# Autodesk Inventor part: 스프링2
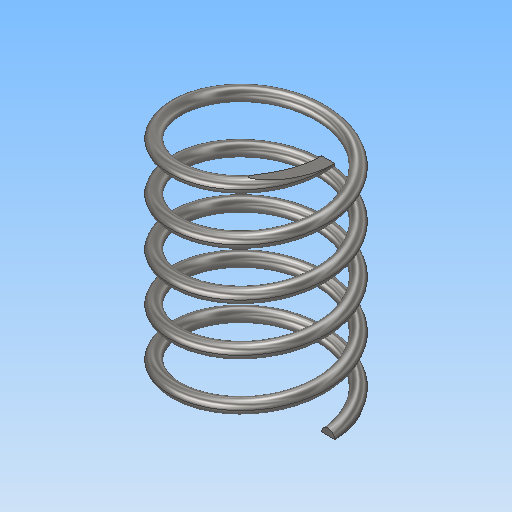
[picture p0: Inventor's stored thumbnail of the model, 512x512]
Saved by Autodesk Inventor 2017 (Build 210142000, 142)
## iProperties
Part Number: 스프링2
Material: 강철, 연강
Document SubType Name: Modeling
Designer: MRC
Density: 7.85 g/cm^3
Appearance: 반연마
Mass: 8.42324 g
Surface Area: 21.7217 cm^2
Volume: 1.07302 cm^3
Author: MRC
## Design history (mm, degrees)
sketch "스케치1"
  geometry: L1 (0, 0)-(0, 36.411); L2 (0, 36.411)-(11, 36.411); L3 (0, 0)-(11, 0); C1 r 1 at (11, 0)
  constraints: 6 end point, 2 horizontal, 1 centre point, 1 coincident, 1 vertical
  dimensions: "d0" = 36.4112 distance of L1.start L1.end (derived); "d2" = 22 diameter of L3.end L1; "d3" = 2 diameter of C1; "d4" = 22 diameter of L2.end L1
feature "코일1" pitch "d5" = 10; turns "d7" = 5; dims "d6" = 36.4112 (= d0), "d8" = 0, angle "d9" = 90 deg, angle "d10" = 90 deg, "d11" = 0, "d12" = 0
sketch "스케치2"
  geometry: L1 (-13.313, 0)-(15.035, 0); L2 (15.035, 0)-(15.035, 36.411); L3 (15.035, 36.411)-(-13.313, 36.411); L4 (-13.313, 36.411)-(-13.313, 0); 1 further point
  constraints: 8 end point, 2 parallel, 1 horizontal, 1 perpendicular
  dimensions: "d13" = 36.4112 distance of L1.end L2.end (= d0)
extrude "돌출1" sketch "스케치2" stored distance "d14" = 0; taper "d15" = 0 deg
node "솔리드1"
